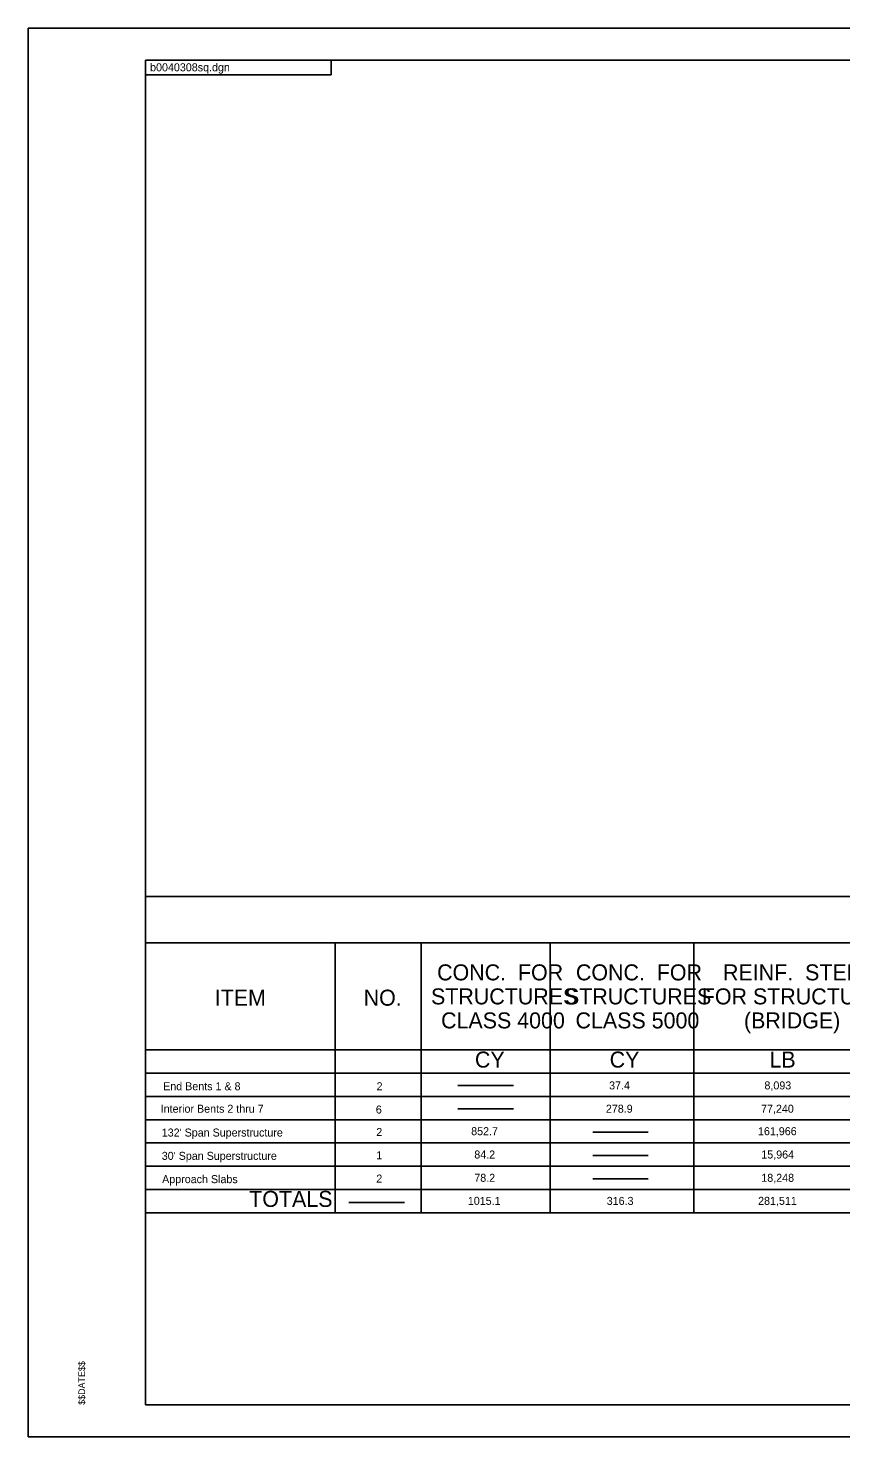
# Model space of a CAD drawing. Extents: x 1334.3 to 1370.4, y 717.9 to 739.9.
# Drawn here: x 1334.33 to 1347.02, y 717.86 to 739.87 of the extents above; entities that cross this region are included whole.
import ezdxf

# ---------------------------------------------------------------- set-up
doc = ezdxf.new("R2010")
doc.units = 0
for name, color, linetype in [('BR_BORDER LINES', 7, 'Continuous'), ('BR_TABLE LINES', 7, 'Continuous'), ('BR_TEXT', 7, 'Continuous'), ('RD_SHT_IplotShp', 7, 'Continuous')]:
    doc.layers.add(name, color=color, linetype=linetype)

msp = doc.modelspace()

# ---------------------------------------------------------------- linework, layer by layer
at = {"layer": 'BR_BORDER LINES'}
for p, q in [((1334.334, 739.866), (1370.334, 739.866)), ((1336.167, 718.365), (1336.167, 739.365)), ((1369.834, 739.365), (1336.167, 739.365)), ((1339.067, 739.365), (1339.067, 739.139)), ((1336.167, 739.139), (1339.067, 739.139)), ((1336.167, 726.305), (1336.167, 721.363)), ((1369.834, 726.305), (1336.167, 726.305)), ((1369.834, 725.579), (1336.167, 725.579)), ((1369.834, 721.363), (1336.167, 721.363)), ((1336.167, 718.365), (1369.834, 718.365)), ((1334.334, 717.866), (1370.334, 717.866))]:
    msp.add_line(p, q, dxfattribs=at)
at = {"layer": 'BR_TABLE LINES'}
for p, q in [((1339.126, 725.579), (1339.126, 721.363)), ((1340.47, 725.579), (1340.47, 721.363)), ((1342.488, 725.579), (1342.488, 721.363)), ((1344.728, 725.579), (1344.728, 721.363)), ((1341.868, 723.91), (1336.167, 723.91)), ((1345.152, 723.91), (1340.47, 723.91)), ((1369.834, 723.91), (1345.152, 723.91)), ((1341.868, 723.546), (1336.167, 723.546)), ((1345.152, 723.546), (1340.47, 723.546)), ((1369.834, 723.546), (1345.152, 723.546)), ((1369.834, 723.182), (1336.167, 723.182)), ((1341.868, 722.818), (1336.167, 722.818)), ((1345.152, 722.818), (1340.47, 722.818)), ((1369.834, 722.818), (1345.152, 722.818)), ((1341.868, 722.455), (1336.167, 722.455)), ((1369.834, 722.455), (1340.47, 722.455)), ((1341.868, 722.091), (1336.167, 722.091)), ((1345.152, 722.091), (1340.47, 722.091)), ((1369.834, 722.091), (1345.152, 722.091)), ((1341.868, 721.727), (1336.167, 721.727)), ((1345.152, 721.727), (1340.47, 721.727)), ((1369.834, 721.727), (1345.152, 721.727))]:
    msp.add_line(p, q, dxfattribs=at)
at = {"layer": 'BR_TEXT'}
for p, q in [((1341.045, 723.35), (1341.913, 723.35)), ((1341.045, 722.986), (1341.913, 722.986)), ((1343.15, 722.622), (1344.017, 722.622)), ((1343.15, 722.259), (1344.017, 722.259)), ((1343.15, 721.895), (1344.017, 721.895)), ((1339.342, 721.527), (1340.209, 721.527))]:
    msp.add_line(p, q, dxfattribs=at)
at = {"layer": 'RD_SHT_IplotShp'}
msp.add_lwpolyline([(1334.334, 739.865), (1370.334, 739.865), (1370.334, 717.865), (1334.334, 717.865)], close=True, dxfattribs=at)

# ---------------------------------------------------------------- texts
at = {"layer": 'BR_TEXT'}
for s, height, p in [('b0040308sq.dgn', 0.125, (1336.238, 739.193)), ('CONC.  FOR ', 0.25, (1340.72, 724.994)), ('CONC.  FOR ', 0.25, (1342.888, 724.994)), ('REINF.  STEEL', 0.25, (1345.185, 724.994)), ('ITEM', 0.25, (1337.248, 724.599)), ('NO.', 0.25, (1339.573, 724.599)), ('STRUCTURES', 0.25, (1340.625, 724.619)), ('STRUCTURES', 0.25, (1342.717, 724.619)), ('FOR STRUCTURES', 0.25, (1344.854, 724.619)), ('(BRIDGE)', 0.25, (1345.512, 724.244)), ('CLASS 4000', 0.25, (1340.782, 724.244)), ('CLASS 5000', 0.25, (1342.882, 724.244)), ('CY', 0.25, (1341.311, 723.632)), ('CY', 0.25, (1343.415, 723.632)), ('LB', 0.25, (1345.911, 723.632)), ('End Bents 1 & 8', 0.125, (1336.442, 723.278)), ('37.4', 0.125, (1343.406, 723.291)), ('8,093', 0.125, (1345.832, 723.291)), ('2', 0.125, (1339.775, 723.278)), ('Interior Bents 2 thru 7', 0.125, (1336.404, 722.927)), ('6', 0.125, (1339.763, 722.914)), ('278.9', 0.125, (1343.356, 722.927)), ('77,240', 0.125, (1345.779, 722.927)), ("132' Span Superstructure", 0.125, (1336.42, 722.555)), ('2', 0.125, (1339.77, 722.563)), ('852.7', 0.125, (1341.252, 722.576)), ('161,966', 0.125, (1345.731, 722.576)), ("30' Span Superstructure", 0.125, (1336.42, 722.191)), ('1', 0.125, (1339.77, 722.199)), ('84.2', 0.125, (1341.301, 722.212)), ('15,964', 0.125, (1345.783, 722.212)), ('Approach Slabs', 0.125, (1336.426, 721.827)), ('2', 0.125, (1339.77, 721.836)), ('78.2', 0.125, (1341.301, 721.848)), ('18,248', 0.125, (1345.783, 721.848)), ('TOTALS', 0.25, (1337.786, 721.456)), ('1015.1', 0.125, (1341.2, 721.488)), ('316.3', 0.125, (1343.369, 721.487)), ('281,511', 0.125, (1345.733, 721.488))]:
    msp.add_text(s, height=height, dxfattribs=at).set_placement(p)
msp.add_text('$$DATE$$', height=0.1042, rotation=90, dxfattribs=at).set_placement((1335.222, 718.365))

doc.saveas('drawing.dxf')
